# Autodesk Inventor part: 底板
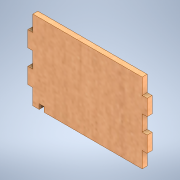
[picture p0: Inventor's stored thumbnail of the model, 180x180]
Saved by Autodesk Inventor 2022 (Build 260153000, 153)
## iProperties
Created: 2024-11
Part Number: 底板
Material: MDF 中密度繊維ボード
Document SubType Name: Modeling
Designer: shimizu
Density: 0.8 g/cm^3
Appearance: サクラ材 - ナチュラル 抑えた光沢
Author: shimizu
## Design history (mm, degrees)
sketch "スケッチ1"
  geometry: L1 (-25.119, 10.226)-(29.881, 10.226); L2 (29.881, -29.774)-(-25.119, -29.774); L3 (-25.119, 2.226)-(-27.619, 2.226); L4 (-27.619, 2.226)-(-27.619, -5.774); L5 (-27.619, -5.774)-(-25.119, -5.774); L6 (-25.119, -13.774)-(-27.619, -13.774); L7 (-27.619, -13.774)-(-27.619, -21.774); L8 (-27.619, -21.774)-(-25.119, -21.774); L9 (29.881, 2.226)-(32.381, 2.226); L10 (32.381, 2.226)-(32.381, -5.774); L11 (32.381, -5.774)-(29.881, -5.774); L12 (29.881, -13.774)-(32.381, -13.774); L13 (32.381, -13.774)-(32.381, -21.774); L14 (32.381, -21.774)-(29.881, -21.774); L15 (-25.119, 2.226)-(-25.119, 10.226); L16 (-25.119, -29.774)-(-25.119, -21.774); L17 (-25.119, -13.774)-(-25.119, -5.774); L18 (29.881, 10.226)-(29.881, 2.226); L19 (29.881, -5.774)-(29.881, -13.774); L20 (29.881, -21.774)-(29.881, -29.774); L21 (-21.939, -29.774)-(-19.429, -29.774); L22 (-19.429, -29.774)-(-19.429, -27.274); L23 (-19.429, -27.274)-(-21.939, -27.274); L24 (-21.939, -27.274)-(-21.939, -29.774); 2 further points
  constraints: 48 end point, 16 parallel, 8 perpendicular, 6 horizontal, 1 point on line
  dimensions: "d16" = 60 distance between parallel lines of L13 L7; "d17" = 2.51 distance between parallel lines of L22 L24; "d18" = 2.5 distance between parallel lines of L2 L23; "d19" = 3.18 distance between parallel lines of L16 L24
extrude "押し出し1" new body sketch "スケッチ1" distance "d2" = 2.5; taper "d3" = 0 deg
node "ソリッド1"
